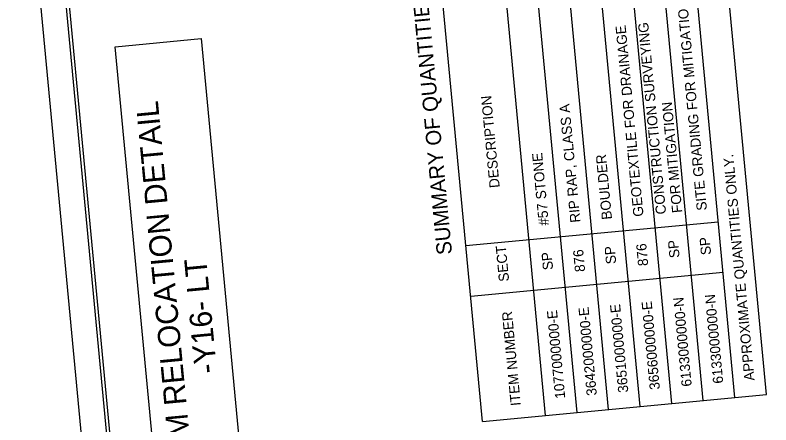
# Model space of a CAD drawing. Extents: x 554635 to 555260, y 497951 to 498841.
# Drawn here: x 554635.2 to 554933.4, y 498517.4 to 498678.9 of the extents above; entities that cross this region are included whole.
import ezdxf

# ---------------------------------------------------------------- set-up
doc = ezdxf.new("R2010")
doc.units = 0
for name, color, linetype in [('Prop NEU Vane Rock Cross With Step Pools Detail CELL', 7, 'Continuous'), ('Prop Plan Preparation Table Ditch Data CELL', 7, 'Continuous'), ('Sheet Plan CELL', 7, 'Continuous'), ('Sheet Plot Border Inside CELL', 7, 'Continuous'), ('Sheet Plot Border Outside CELL', 7, 'Continuous')]:
    doc.layers.add(name, color=color, linetype=linetype)

msp = doc.modelspace()

# ---------------------------------------------------------------- linework, layer by layer
at = {"layer": 'Prop NEU Vane Rock Cross With Step Pools Detail CELL'}
msp.add_lwpolyline([(554693.71, 498465.77), (554674.74, 498666.49), (554708.62, 498669.7), (554727.59, 498468.97)], close=True, dxfattribs=at)
at = {"layer": 'Prop Plan Preparation Table Ditch Data CELL'}
for p, q in [((554919.18, 498528.18), (554896.59, 498767.12)), ((554931.63, 498529.36), (554909.04, 498768.29)), ((554894.29, 498525.83), (554871.7, 498764.76)), ((554906.74, 498527.01), (554884.15, 498765.94)), ((554856.96, 498522.3), (554834.37, 498761.23)), ((554869.4, 498523.48), (554846.82, 498762.41)), ((554881.85, 498524.65), (554859.26, 498763.59)), ((554844.52, 498521.12), (554821.93, 498760.06)), ((554813.07, 498588.1), (554912.63, 498597.51)), ((554814.96, 498568.18), (554914.51, 498577.59)), ((554819.63, 498518.77), (554931.63, 498529.36))]:
    msp.add_line(p, q, dxfattribs=at)
msp.add_lwpolyline([(554819.63, 498518.77), (554797.04, 498757.71), (554909.04, 498768.29)], dxfattribs=at)
at = {"layer": 'Sheet Plan CELL'}
msp.add_lwpolyline([(554647.23, 498781.63), (554717.82, 498034.95), (555240.49, 498084.36), (555169.9, 498831.04)], close=True, dxfattribs=at)
at = {"layer": 'Sheet Plot Border Inside CELL'}
msp.add_lwpolyline([(555248.96, 498008.08), (555170.55, 498837.37), (554645.4, 498787.73), (554723.81, 497958.43)], close=True, dxfattribs=at)
at = {"layer": 'Sheet Plot Border Outside CELL'}
msp.add_lwpolyline([(555259.53, 498002.55), (555180.3, 498840.56), (554635.23, 498789.03), (554714.46, 497951.01)], close=True, dxfattribs=at)

# ---------------------------------------------------------------- texts
at = {"layer": 'Prop NEU Vane Rock Cross With Step Pools Detail CELL'}
for s, height, p in [('STREAM RELOCATION DETAIL', 8.7608, (554707.79, 498473.67)), ('-Y16- LT', 8.761, (554714.91, 498538.02))]:
    msp.add_text(s, height=height, rotation=95.4008, dxfattribs=at).set_placement(p)
at = {"layer": 'Prop Plan Preparation Table Ditch Data CELL'}
for s, height, p in [('SUMMARY OF QUANTITIES', 6, (554807.64, 498584.74)), ('SITE GRADING FOR MITIGATION', 4, (554908.19, 498602.07)), ('GEOTEXTILE FOR DRAINAGE', 4, (554883.19, 498599.67)), ('CONSTRUCTION SURVEYING ', 4, (554892.1, 498600.55)), ('DESCRIPTION', 4, (554826.44, 498611)), ('RIP RAP, CLASS A', 4, (554858.3, 498597.32)), ('FOR MITIGATION', 4, (554898.47, 498601.15)), ('#57 STONE', 4, (554845.85, 498596.14)), ('BOULDER', 4, (554870.74, 498598.5)), ('APPROXIMATE QUANTITIES ONLY.', 4, (554926.97, 498534.99)), ('SP', 4, (554909.85, 498584.55)), ('876', 4, (554885.03, 498580.22)), ('SP', 4, (554897.41, 498583.38)), ('SECT', 4, (554830.14, 498574.07)), ('SP', 4, (554847.51, 498578.62)), ('876', 4, (554860.14, 498577.87)), ('SP', 4, (554872.4, 498580.98)), ('6133000000-N', 4, (554902.2, 498532.69)), ('6133000000-N', 4, (554914.64, 498533.86)), ('3651000000-E', 4, (554877.19, 498530.29)), ('3656000000-E', 4, (554889.64, 498531.46)), ('ITEM NUMBER', 4, (554834.77, 498525.1)), ('1077000000-E', 4, (554852.3, 498527.93)), ('3642000000-E', 4, (554864.75, 498529.11))]:
    msp.add_text(s, height=height, rotation=95.4008, dxfattribs=at).set_placement(p)

doc.saveas('drawing.dxf')
